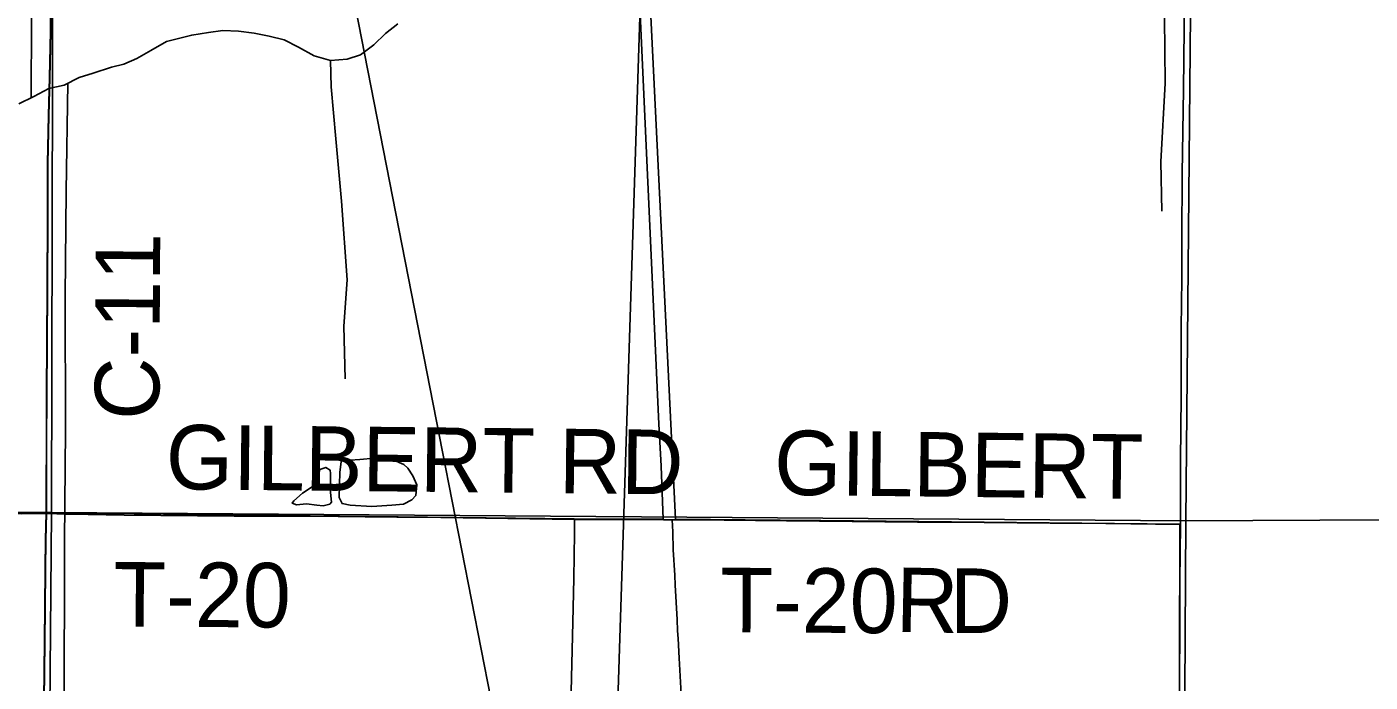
# Model space of a CAD drawing. Extents: x 0 to 34, y 0 to 22.
# Drawn here: x 3.48 to 4.664, y 17.907 to 18.485 of the extents above; entities that cross this region are included whole.
import ezdxf

# ---------------------------------------------------------------- set-up
doc = ezdxf.new("R2010")
doc.units = 0
for name, color, linetype in [('GM_X_City_Street', 7, 'Continuous'), ('GM_X_Corporation', 7, 'Continuous'), ('GM_X_County_Road', 7, 'Continuous'), ('GM_X_County_Road_Text', 7, 'Continuous'), ('GM_X_Major_River', 7, 'Continuous'), ('GM_X_Minor_Lake', 7, 'Continuous'), ('GM_X_Minor_River', 7, 'Continuous'), ('GM_X_Rail_Line', 7, 'Continuous'), ('GM_X_Section', 7, 'Continuous'), ('GM_X_State_Route', 7, 'Continuous'), ('GM_X_Township_Road', 7, 'Continuous'), ('GM_X_Township_Road_Text', 7, 'Continuous'), ('GM_X_US_Route', 7, 'Continuous')]:
    doc.layers.add(name, color=color, linetype=linetype)

msp = doc.modelspace()

# ---------------------------------------------------------------- linework, layer by layer
at = {"layer": 'GM_X_City_Street'}
for points in [[(3.963, 17.795), (3.962, 17.7976), (3.9614, 17.7993), (3.9608, 17.8014), (3.9601, 17.8039), (3.9596, 17.8077), (3.9595, 17.8114), (3.9592, 17.832), (3.9594, 17.8479), (3.9596, 17.887), (3.9613, 17.9602), (3.9621, 17.9987), (3.9626, 18.0388), (3.9627, 18.0507)], [(4.0615, 17.7983), (4.0611, 17.8059), (4.0603, 17.8233), (4.0581, 17.8673), (4.0572, 17.8864), (4.0555, 17.9181), (4.0549, 17.9286), (4.0539, 17.9459), (4.0535, 17.9527), (4.053, 17.9627), (4.0514, 17.993), (4.051, 18.0017), (4.0497, 18.024), (4.0492, 18.0399), (4.0488, 18.0504)]]:
    msp.add_lwpolyline(points, dxfattribs=at)
at = {"layer": 'GM_X_Corporation'}
for points in [[(3.4944, 17.795), (3.4956, 17.9163), (3.4972, 18.0567), (3.9625, 18.0513), (4.0408, 18.0511), (4.0391, 18.0978), (4.0371, 18.1351), (4.0177, 18.5611)], [(4.0268, 18.5601), (4.0518, 18.0509), (4.1746, 18.0498), (4.1797, 18.05), (4.4959, 18.0466), (4.4954, 17.796)]]:
    msp.add_lwpolyline(points, dxfattribs=at)
at = {"layer": 'GM_X_County_Road'}
for points in [[(3.4975, 18.0561), (3.4974, 18.0744), (3.4976, 18.1229), (3.4977, 18.1559), (3.498, 18.2112), (3.4984, 18.2491), (3.4986, 18.3219), (3.4986, 18.3642), (3.499, 18.3783), (3.4995, 18.4063), (3.5005, 18.4398), (3.5013, 18.4802), (3.5016, 18.5088)], [(3.4939, 17.733), (3.4939, 17.736), (3.4942, 17.7596), (3.4946, 17.7944), (3.4947, 17.8349), (3.4952, 17.8697), (3.4958, 17.9157), (3.4964, 17.9723), (3.4966, 18.0071), (3.497, 18.0326), (3.4975, 18.0561)]]:
    msp.add_lwpolyline(points, dxfattribs=at)
at = {"layer": 'GM_X_Major_River'}
msp.add_lwpolyline([(3.8071, 18.4875), (3.7963, 18.479), (3.7858, 18.469), (3.7742, 18.4602), (3.7625, 18.4562), (3.7476, 18.4552), (3.7333, 18.4593), (3.7195, 18.4668), (3.7068, 18.4732), (3.6936, 18.4766), (3.6804, 18.4792), (3.6668, 18.481), (3.6528, 18.4814), (3.6403, 18.4798), (3.6255, 18.4775), (3.6034, 18.4719), (3.5895, 18.4639), (3.5772, 18.457), (3.5657, 18.452), (3.5547, 18.4492), (3.5387, 18.4439), (3.5264, 18.44), (3.513, 18.4335), (3.4997, 18.4304), (3.4863, 18.4235), (3.4732, 18.417)], dxfattribs=at)
at = {"layer": 'GM_X_Minor_Lake'}
for p, q in [((3.7476, 18.0745), (3.7477, 18.0912)), ((3.756, 18.0925), (3.7555, 18.0701))]:
    msp.add_line(p, q, dxfattribs=at)
for points in [[(3.7477, 18.0912), (3.7474, 18.0942), (3.7436, 18.0966), (3.7383, 18.0948), (3.7362, 18.0854), (3.7315, 18.0795), (3.723, 18.074), (3.7153, 18.0673), (3.7141, 18.0651), (3.7178, 18.0638), (3.7265, 18.0644), (3.7356, 18.0634), (3.7413, 18.0629), (3.747, 18.0643), (3.7486, 18.0661), (3.7476, 18.0745)], [(3.7555, 18.0701), (3.758, 18.0648), (3.7651, 18.0635), (3.7841, 18.0622), (3.8019, 18.0633), (3.8121, 18.0642), (3.8194, 18.0682), (3.8229, 18.0719), (3.8239, 18.0814), (3.8203, 18.0891), (3.8159, 18.096), (3.8122, 18.0991), (3.8014, 18.1039), (3.7862, 18.1047), (3.7737, 18.1035), (3.765, 18.1029), (3.7574, 18.1039), (3.756, 18.0925)]]:
    msp.add_lwpolyline(points, dxfattribs=at)
at = {"layer": 'GM_X_Minor_River'}
for points in [[(3.4839, 18.4224), (3.4847, 18.5579), (3.4847, 18.6657), (3.4855, 18.7761), (3.4868, 18.8858), (3.4855, 19.0338)], [(4.4832, 18.5994), (4.482, 18.5505), (4.4829, 18.4351), (4.4793, 18.3657), (4.4801, 18.3224)], [(3.7476, 18.4552), (3.7482, 18.432), (3.7523, 18.386), (3.7574, 18.3312), (3.7625, 18.262), (3.7596, 18.2211), (3.7607, 18.1748)], [(3.5164, 18.4352), (3.5149, 18.3401), (3.5141, 18.2475), (3.5142, 18.1295), (3.5133, 18.0316), (3.5132, 17.8764), (3.5078, 17.8723), (3.5098, 17.8139), (3.5136, 17.7098), (3.5131, 17.6286), (3.5084, 17.5585), (3.5105, 17.5083), (3.5084, 17.4393), (3.5067, 17.3399)]]:
    msp.add_lwpolyline(points, dxfattribs=at)
at = {"layer": 'GM_X_Rail_Line'}
for points in [[(3.0707, 20.9), (3.1351, 20.7649), (3.2934, 20.4339), (3.3742, 20.2628), (3.4243, 20.1498), (3.4485, 20.0723), (3.4792, 19.9786), (3.5083, 19.83), (3.6846, 18.9371), (3.8463, 18.1103), (4.0848, 16.8935)], [(4.0191, 20.9), (4.0122, 20.3656), (4.0051, 19.4649), (4.0042, 19.0681), (4.0247, 18.6307), (3.9918, 17.6084), (3.9918, 17.4265), (4.095, 16.8935)]]:
    msp.add_lwpolyline(points, dxfattribs=at)
at = {"layer": 'GM_X_Section'}
for points in [[(3.5044, 19.0749), (3.5019, 18.057), (2.4915, 18.0628), (2.4993, 19.0815)], [(4.5106, 19.0706), (4.5012, 18.0497), (3.5019, 18.057), (3.5044, 19.0749)], [(5.5091, 19.0615), (5.5052, 18.0545), (4.5012, 18.0497), (4.5106, 19.0706)], [(3.5019, 18.057), (3.4934, 17.0475), (2.4879, 17.0483), (2.4915, 18.0628)], [(4.5012, 18.0497), (4.4954, 17.0428), (3.4934, 17.0475), (3.5019, 18.057)], [(5.5052, 18.0545), (5.4985, 17.0434), (4.4954, 17.0428), (4.5012, 18.0497)]]:
    msp.add_lwpolyline(points, close=True, dxfattribs=at)
at = {"layer": 'GM_X_State_Route'}
for points in [[(2.1, 18.0629), (2.1654, 18.0625), (2.198, 18.0623), (2.2695, 18.0621), (2.313, 18.0623), (2.372, 18.0625), (2.4559, 18.0623), (2.4932, 18.0623), (2.5212, 18.0621), (2.6253, 18.0616), (2.6921, 18.0614), (2.8211, 18.0604), (2.9283, 18.0596), (3.0076, 18.059), (3.0558, 18.0585), (3.1024, 18.0582), (3.1723, 18.0579), (3.2531, 18.0572), (3.2826, 18.057), (3.3479, 18.0565), (3.4318, 18.0561), (3.4753, 18.0558), (3.4975, 18.0561)], [(3.4975, 18.0561), (3.497, 18.0326), (3.4966, 18.0071), (3.4964, 17.9723), (3.4958, 17.9157), (3.4952, 17.8697), (3.4947, 17.8349), (3.4946, 17.7944), (3.4942, 17.7596), (3.4939, 17.736), (3.4939, 17.733)]]:
    msp.add_lwpolyline(points, dxfattribs=at)
at = {"layer": 'GM_X_Township_Road'}
for p, q in [((4.041, 18.0505), (4.0488, 18.0504)), ((4.0488, 18.0504), (4.052, 18.0504))]:
    msp.add_line(p, q, dxfattribs=at)
for points in [[(4.4966, 18.0464), (4.4965, 18.1014), (4.4969, 18.1317), (4.497, 18.1584), (4.497, 18.1926), (4.4972, 18.2193), (4.4976, 18.2628), (4.4978, 18.2979), (4.498, 18.3557), (4.4991, 18.4297), (4.5004, 18.5366), (4.5008, 18.5752), (4.5012, 18.5982), (4.5019, 18.6759), (4.5026, 18.7499), (4.5029, 18.7841), (4.5042, 18.8487), (4.5057, 18.9146), (4.5062, 18.9444), (4.5065, 18.9693), (4.507, 19.0296), (4.5069, 19.065), (4.507, 19.0731)], [(3.4975, 18.0561), (3.5066, 18.0557), (3.5137, 18.0555), (3.5184, 18.0554), (3.5659, 18.0547), (3.6628, 18.0538), (3.7305, 18.0537), (3.7784, 18.053), (3.8063, 18.0527), (3.8449, 18.0524), (3.9627, 18.0507)], [(3.9627, 18.0507), (3.9738, 18.0507), (4.003, 18.0507), (4.0073, 18.0506), (4.041, 18.0505)], [(4.052, 18.0504), (4.0673, 18.0504), (4.1494, 18.0495), (4.2072, 18.0489), (4.2648, 18.0484), (4.2946, 18.0483), (4.3816, 18.0474), (4.4307, 18.0471), (4.4966, 18.0464)], [(4.4957, 17.7954), (4.496, 17.8176), (4.4959, 17.8388), (4.4958, 17.868), (4.4961, 17.9965), (4.4966, 18.0464)]]:
    msp.add_lwpolyline(points, dxfattribs=at)
at = {"layer": 'GM_X_US_Route'}
for points in [[(3.495, 17.8702), (3.4956, 17.9163), (3.4962, 17.9728), (3.4964, 18.0077), (3.4968, 18.0332), (3.4972, 18.0567), (3.4972, 18.0749), (3.4974, 18.1235), (3.4975, 18.1564), (3.4978, 18.2117), (3.4982, 18.2497), (3.4984, 18.3224), (3.4984, 18.3647), (3.4988, 18.3789), (3.4992, 18.4068), (3.5003, 18.4404), (3.5011, 18.4808), (3.5014, 18.5094)], [(3.5014, 18.5094), (3.5011, 18.4808), (3.5003, 18.4404), (3.4992, 18.4068), (3.4988, 18.3789), (3.4984, 18.3647), (3.4984, 18.3224), (3.4982, 18.2497), (3.4978, 18.2117), (3.4975, 18.1564), (3.4974, 18.1235), (3.4972, 18.0749), (3.4972, 18.0567), (3.4968, 18.0332), (3.4964, 18.0077), (3.4962, 17.9728), (3.4956, 17.9163), (3.495, 17.8702)]]:
    msp.add_lwpolyline(points, dxfattribs=at)

# ---------------------------------------------------------------- texts
at = {"layer": 'GM_X_County_Road_Text'}
msp.add_text('C-11', height=0.05682, rotation=89.6656, dxfattribs=at).set_placement((3.5968, 18.1384))
at = {"layer": 'GM_X_Township_Road_Text'}
for s, height, rotation, p in [('GILBERT RD', 0.05682, 359.4123, (3.6025, 18.0775)), ('GILBERT', 0.05682, 359.3519, (4.1384, 18.0725)), ('T-20', 0.05682, 359.6516, (3.5564, 17.9565)), ('T-20', 0.05682, 359.6457, (4.091, 17.9515)), ('R', 0.0568, 358.8446, (4.2454, 17.9518)), ('D', 0.0568, 359.9664, (4.2933, 17.9508))]:
    msp.add_text(s, height=height, rotation=rotation, dxfattribs=at).set_placement(p)

doc.saveas('drawing.dxf')
